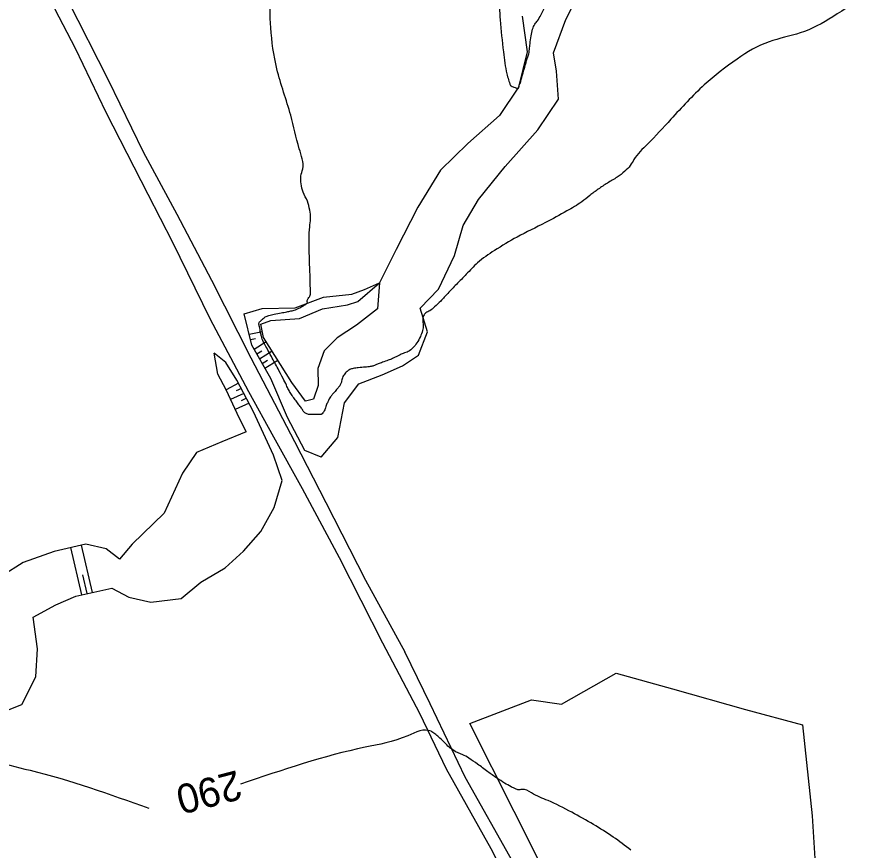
# Model space of a CAD drawing. Extents: x -475575 to -473225, y -1116053 to -1114104.
# Drawn here: x -473778.6 to -473663.7, y -1115005.8 to -1114891.8 of the extents above; entities that cross this region are included whole.
import ezdxf

# ---------------------------------------------------------------- set-up
doc = ezdxf.new("R2010")
doc.units = 0
for name, color, linetype in [('Vrstevnice_hlavni', 7, 'Continuous'), ('Vrstevnice_popis', 7, 'Continuous'), ('Vrstevnice_vedlejsi', 7, 'Continuous'), ('Vrstva_10', 7, 'Continuous')]:
    doc.layers.add(name, color=color, linetype=linetype)

msp = doc.modelspace()

# ---------------------------------------------------------------- linework, layer by layer
at = {"layer": 'Vrstevnice_hlavni'}
for points in [[(-473788.48, -1114990.57), (-473787.7, -1114989.85), (-473787.05, -1114989.73), (-473786.53, -1114990.19), (-473786.14, -1114991.25), (-473785.78, -1114991.95), (-473785.46, -1114992.29), (-473785.18, -1114992.26), (-473782.28, -1114993.11), (-473776.78, -1114994.83), (-473760.55, -1115000.02)], [(-473694.62, -1115005.76), (-473697.04, -1115003.96), (-473699.74, -1115002.24), (-473702.71, -1115000.57), (-473705.95, -1114998.97), (-473708.22, -1114997.93), (-473709.5, -1114997.44), (-473709.81, -1114997.51), (-473710.31, -1114997.39), (-473711.01, -1114997.08), (-473711.89, -1114996.58), (-473712.95, -1114995.9), (-473714.19, -1114995.03), (-473715.6, -1114993.98), (-473716.76, -1114993.19), (-473717.67, -1114992.68), (-473718.33, -1114992.42), (-473718.98, -1114992.04), (-473719.64, -1114991.51), (-473720.29, -1114990.85), (-473720.89, -1114990.29), (-473721.45, -1114989.84), (-473721.95, -1114989.5), (-473725.13, -1114990.11), (-473730.97, -1114991.68), (-473748.01, -1114996.73)], [(-473766.29, -1115102.81), (-473766.71, -1115101.56), (-473767.08, -1115100.43), (-473767.41, -1115099.41), (-473767.7, -1115098.51), (-473768.04, -1115097.46), (-473768.45, -1115096.25), (-473768.91, -1115094.88), (-473769.29, -1115093.72), (-473769.59, -1115092.77), (-473769.8, -1115092.02), (-473770.06, -1115091.24), (-473770.35, -1115090.42), (-473770.68, -1115089.57), (-473771.1, -1115088.3), (-473771.62, -1115086.63), (-473772.24, -1115084.54), (-473772.75, -1115082.84), (-473773.16, -1115081.53), (-473773.46, -1115080.61), (-473773.69, -1115079.78), (-473773.86, -1115079.05), (-473773.96, -1115078.4), (-473774.21, -1115077.4), (-473774.61, -1115076.04), (-473775.15, -1115074.31), (-473775.57, -1115072.9), (-473775.87, -1115071.82), (-473776.05, -1115071.05), (-473776.24, -1115070.27), (-473776.46, -1115069.47), (-473776.7, -1115068.65), (-473777.04, -1115067.5), (-473777.48, -1115066.01), (-473778.01, -1115064.19), (-473778.45, -1115062.69), (-473778.81, -1115061.51), (-473779.09, -1115060.64), (-473779.43, -1115059.49), (-473779.84, -1115058.06), (-473780.31, -1115056.33), (-473780.78, -1115054.75), (-473781.24, -1115053.31), (-473781.69, -1115052.02), (-473782.08, -1115050.93), (-473782.41, -1115050.06), (-473782.67, -1115049.4), (-473782.99, -1115048.4), (-473783.38, -1115047.05), (-473783.84, -1115045.35), (-473784.21, -1115043.9), (-473784.5, -1115042.7), (-473784.7, -1115041.74), (-473784.98, -1115040.58), (-473785.32, -1115039.22), (-473785.72, -1115037.66), (-473786.11, -1115036.27), (-473786.47, -1115035.06), (-473786.82, -1115034.02), (-473787.13, -1115032.91), (-473787.42, -1115031.73), (-473787.68, -1115030.48), (-473787.94, -1115029.23), (-473788.22, -1115027.98), (-473788.51, -1115026.74), (-473788.81, -1115025.47), (-473789.12, -1115024.19), (-473789.45, -1115022.88), (-473789.79, -1115021.56), (-473790.15, -1115020.23), (-473790.52, -1115018.88), (-473790.9, -1115017.5), (-473791.28, -1115016.07), (-473791.67, -1115014.61), (-473792.04, -1115013.08), (-473792.4, -1115011.48), (-473792.74, -1115009.82), (-473793.01, -1115008.27), (-473793.21, -1115006.83), (-473793.33, -1115005.52), (-473793.42, -1115004.39), (-473793.49, -1115003.44), (-473793.52, -1115002.69), (-473793.69, -1115001.84), (-473794, -1115000.92), (-473794.45, -1114999.91), (-473794.77, -1114999.16), (-473794.95, -1114998.68), (-473794.99, -1114998.45), (-473795.09, -1114998.06), (-473795.24, -1114997.52), (-473795.43, -1114996.81), (-473794.85, -1114995.8), (-473793.5, -1114994.49), (-473791.38, -1114992.89), (-473789.71, -1114991.58), (-473788.48, -1114990.57)]]:
    msp.add_spline(points, degree=3, dxfattribs=at)
at = {"layer": 'Vrstevnice_vedlejsi'}
for points in [[(-473806.43, -1114819.38), (-473806.38, -1114819.37), (-473806.1, -1114819.33), (-473805.58, -1114819.26), (-473804.83, -1114819.16), (-473804.26, -1114819.08), (-473803.86, -1114819.01), (-473803.64, -1114818.96), (-473803.42, -1114818.89), (-473803.18, -1114818.82), (-473802.94, -1114818.73), (-473802.51, -1114818.57), (-473801.87, -1114818.32), (-473801.04, -1114817.99), (-473800.27, -1114817.66), (-473799.56, -1114817.32), (-473798.92, -1114816.98), (-473798.15, -1114816.62), (-473797.28, -1114816.25), (-473796.28, -1114815.85), (-473795.35, -1114815.35), (-473794.47, -1114814.75), (-473793.65, -1114814.03), (-473792.88, -1114813.39), (-473792.17, -1114812.84), (-473791.51, -1114812.36), (-473790.85, -1114811.93), (-473790.2, -1114811.53), (-473789.56, -1114811.17), (-473789.11, -1114810.81), (-473788.86, -1114810.45), (-473788.79, -1114810.08), (-473788.78, -1114809.72), (-473788.8, -1114809.36), (-473788.87, -1114809.01), (-473788.92, -1114808.76), (-473788.96, -1114808.61), (-473788.98, -1114808.58), (-473789.06, -1114808.47), (-473789.2, -1114808.3), (-473789.4, -1114808.07), (-473789.38, -1114807.65), (-473789.15, -1114807.05), (-473788.71, -1114806.27), (-473788.35, -1114805.79), (-473788.06, -1114805.62), (-473787.84, -1114805.76), (-473787.63, -1114805.87), (-473787.42, -1114805.95), (-473787.21, -1114805.99), (-473786.5, -1114806.07), (-473785.28, -1114806.2), (-473783.56, -1114806.36), (-473781.6, -1114806.32), (-473779.4, -1114806.07), (-473776.95, -1114805.61), (-473775.18, -1114805.35), (-473774.08, -1114805.27), (-473773.66, -1114805.39), (-473771.91, -1114806.02), (-473768.82, -1114807.16), (-473764.41, -1114808.81), (-473757.99, -1114812.23), (-473749.55, -1114817.42), (-473739.09, -1114824.39), (-473731.16, -1114829.57), (-473725.76, -1114832.96), (-473722.88, -1114834.56), (-473720.56, -1114835.65), (-473718.79, -1114836.23), (-473717.58, -1114836.3), (-473715.64, -1114836.75), (-473712.97, -1114837.58), (-473709.58, -1114838.79), (-473708.57, -1114839.98), (-473709.95, -1114841.15), (-473713.71, -1114842.3), (-473715.46, -1114846.43), (-473715.18, -1114853.56), (-473712.88, -1114863.69), (-473711.43, -1114870.72), (-473710.84, -1114874.67), (-473711.08, -1114875.53), (-473711.23, -1114876.41), (-473711.26, -1114877.31), (-473711.19, -1114878.25), (-473711.12, -1114879.28), (-473711.05, -1114880.42), (-473710.98, -1114881.65), (-473711.16, -1114883.03), (-473711.59, -1114884.54), (-473712.27, -1114886.19), (-473712.58, -1114888.75), (-473712.5, -1114892.22), (-473712.05, -1114896.6), (-473711.58, -1114899.59), (-473711.1, -1114901.19)], [(-473711.1, -1114901.19), (-473710.61, -1114901.41), (-473710.26, -1114901.54), (-473710.06, -1114901.57), (-473710.01, -1114901.53), (-473709.97, -1114901.49), (-473709.95, -1114901.47), (-473709.94, -1114901.46), (-473709.93, -1114901.44), (-473709.93, -1114901.43), (-473709.93, -1114901.42), (-473709.78, -1114900.89), (-473709.47, -1114899.85), (-473709.01, -1114898.29), (-473708.71, -1114897.24), (-473708.55, -1114896.69), (-473708.55, -1114896.64), (-473708.5, -1114896.23), (-473708.41, -1114895.48), (-473708.27, -1114894.37), (-473708.06, -1114893.47), (-473707.77, -1114892.8), (-473707.4, -1114892.33), (-473706.94, -1114891.55), (-473706.39, -1114890.46), (-473705.74, -1114889.05), (-473705.18, -1114887.94), (-473704.69, -1114887.15), (-473704.29, -1114886.65), (-473703.73, -1114886.18), (-473703.01, -1114885.72), (-473702.14, -1114885.28), (-473701.43, -1114884.84), (-473700.89, -1114884.42), (-473700.52, -1114884.01), (-473700.06, -1114883.38), (-473699.49, -1114882.54), (-473698.82, -1114881.48), (-473698.24, -1114880.31), (-473697.76, -1114879.03), (-473697.37, -1114877.62), (-473697.09, -1114876.65), (-473696.93, -1114876.12), (-473696.88, -1114876.01), (-473696.49, -1114875.69), (-473695.76, -1114875.14), (-473694.69, -1114874.37), (-473693.74, -1114873.74), (-473692.92, -1114873.26), (-473692.23, -1114872.91), (-473690.49, -1114869.83), (-473687.7, -1114864.01), (-473683.85, -1114855.45), (-473680.86, -1114849.41), (-473678.72, -1114845.88), (-473677.43, -1114844.86), (-473675.79, -1114843.76), (-473673.8, -1114842.57), (-473671.44, -1114841.28), (-473668.14, -1114838.94), (-473663.87, -1114835.52), (-473658.65, -1114831.05), (-473653.68, -1114827.13), (-473648.95, -1114823.78), (-473644.48, -1114820.98), (-473640.15, -1114820.2), (-473635.99, -1114821.44), (-473631.98, -1114824.7), (-473626.19, -1114826.58), (-473618.64, -1114827.09), (-473609.32, -1114826.22), (-473599.64, -1114826.28), (-473589.6, -1114827.29), (-473579.21, -1114829.24), (-473571.3, -1114830.25), (-473565.87, -1114830.31), (-473562.94, -1114829.43), (-473557.46, -1114829.21), (-473549.43, -1114829.66), (-473548.19, -1114829.78)], [(-473734.16, -1114941.44), (-473734.2, -1114941.76), (-473734.37, -1114942.13), (-473734.66, -1114942.54), (-473735.07, -1114943.01), (-473735.41, -1114943.41), (-473735.68, -1114943.76), (-473735.87, -1114944.05), (-473736.07, -1114944.44), (-473736.28, -1114944.94), (-473736.49, -1114945.55), (-473736.73, -1114945.96), (-473736.97, -1114946.16), (-473737.23, -1114946.17), (-473737.58, -1114946.17), (-473738.03, -1114946.17), (-473738.58, -1114946.18), (-473739.02, -1114946.05), (-473739.36, -1114945.79), (-473739.6, -1114945.41), (-473739.91, -1114944.96), (-473740.29, -1114944.45), (-473740.73, -1114943.88), (-473741.12, -1114943.31), (-473741.44, -1114942.75), (-473741.71, -1114942.18), (-473742.18, -1114941.24), (-473742.87, -1114939.93), (-473743.77, -1114938.26), (-473744.42, -1114937.06), (-473744.81, -1114936.32), (-473744.95, -1114936.06), (-473745.07, -1114935.71), (-473745.19, -1114935.28), (-473745.29, -1114934.77), (-473745.37, -1114934.36), (-473745.44, -1114934.05), (-473745.48, -1114933.84), (-473745.47, -1114933.66), (-473745.41, -1114933.51), (-473745.28, -1114933.4), (-473745.11, -1114933.24), (-473744.89, -1114933.06), (-473744.61, -1114932.84), (-473744.11, -1114932.64), (-473743.39, -1114932.45), (-473742.43, -1114932.28), (-473741.68, -1114932.13), (-473741.13, -1114932.02), (-473740.78, -1114931.93), (-473740.5, -1114931.85), (-473740.28, -1114931.77), (-473740.12, -1114931.7), (-473739.89, -1114931.58), (-473739.58, -1114931.41), (-473739.2, -1114931.18), (-473738.96, -1114930.99), (-473738.86, -1114930.82), (-473738.9, -1114930.68), (-473738.86, -1114930.51), (-473738.76, -1114930.31), (-473738.58, -1114930.08), (-473738.46, -1114929.85), (-473738.41, -1114929.6), (-473738.42, -1114929.35), (-473738.46, -1114928.36), (-473738.51, -1114926.63), (-473738.59, -1114924.15), (-473738.6, -1114922.12), (-473738.54, -1114920.53), (-473738.42, -1114919.38), (-473738.53, -1114918.21), (-473738.86, -1114917.01), (-473739.42, -1114915.78), (-473739.72, -1114914.63), (-473739.74, -1114913.57), (-473739.49, -1114912.59), (-473739.96, -1114909.83), (-473741.14, -1114905.26), (-473743.03, -1114898.91), (-473743.86, -1114893.28), (-473743.63, -1114888.37), (-473742.33, -1114884.19), (-473743.57, -1114878.62), (-473747.35, -1114871.67), (-473753.68, -1114863.33), (-473758.63, -1114857.18), (-473762.22, -1114853.23), (-473764.43, -1114851.47), (-473766.22, -1114850.1), (-473767.58, -1114849.15), (-473768.51, -1114848.59), (-473769.49, -1114848.05), (-473770.53, -1114847.52), (-473771.62, -1114847.01), (-473773.23, -1114846.47), (-473775.36, -1114845.92)], [(-473526.4, -1114874.11), (-473532.36, -1114874.36), (-473544.72, -1114875.73), (-473553.28, -1114876.61), (-473558.05, -1114877), (-473559.03, -1114876.91), (-473560.16, -1114876.71), (-473561.46, -1114876.41), (-473562.92, -1114876.02), (-473567.85, -1114875.52), (-473576.26, -1114874.92), (-473588.13, -1114874.22), (-473599.38, -1114873.36), (-473610, -1114872.35), (-473619.99, -1114871.17), (-473627.77, -1114870.54), (-473633.33, -1114870.45), (-473636.66, -1114870.9), (-473639.51, -1114871.55), (-473641.86, -1114872.37), (-473643.73, -1114873.39), (-473645.76, -1114874.69), (-473647.95, -1114876.27), (-473650.31, -1114878.14), (-473653.5, -1114880.8), (-473657.51, -1114884.27), (-473662.35, -1114888.54), (-473667, -1114891.78), (-473671.46, -1114894), (-473675.73, -1114895.2), (-473680.1, -1114897.56), (-473684.58, -1114901.1), (-473689.15, -1114905.8), (-473692.36, -1114909.21), (-473694.21, -1114911.31), (-473694.7, -1114912.11), (-473695.46, -1114912.92), (-473696.5, -1114913.72), (-473697.83, -1114914.53), (-473699.08, -1114915.36), (-473700.25, -1114916.22), (-473701.34, -1114917.09), (-473703.36, -1114918.34), (-473706.31, -1114919.94), (-473710.18, -1114921.91), (-473713.27, -1114923.75), (-473715.59, -1114925.44), (-473717.13, -1114927), (-473718.48, -1114928.39), (-473719.65, -1114929.61), (-473720.63, -1114930.66), (-473721.46, -1114931.46), (-473722.13, -1114931.99), (-473722.64, -1114932.26), (-473722.96, -1114932.68), (-473723.08, -1114933.24), (-473723.01, -1114933.95), (-473723.11, -1114934.71), (-473723.41, -1114935.52), (-473723.88, -1114936.39), (-473724.43, -1114937.07), (-473725.06, -1114937.55), (-473725.76, -1114937.83), (-473726.28, -1114938.06), (-473726.64, -1114938.24), (-473726.83, -1114938.35), (-473727.21, -1114938.53), (-473727.8, -1114938.76), (-473728.59, -1114939.04), (-473729.18, -1114939.26), (-473729.59, -1114939.43), (-473729.8, -1114939.52), (-473730.25, -1114939.62), (-473730.95, -1114939.7), (-473731.89, -1114939.78), (-473732.59, -1114939.89), (-473733.06, -1114940.02), (-473733.3, -1114940.18), (-473733.53, -1114940.37), (-473733.73, -1114940.6), (-473733.92, -1114940.86), (-473734.06, -1114941.14), (-473734.16, -1114941.44)]]:
    msp.add_spline(points, degree=3, dxfattribs=at)
at = {"layer": 'Vrstva_10'}
for p, q in [((-473746.83, -1114935.18), (-473745, -1114934.82)), ((-473746.65, -1114935.91), (-473745.93, -1114935.77)), ((-473746.14, -1114937.24), (-473744.49, -1114936.2)), ((-473750.02, -1114939.08), (-473751.61, -1114937.8)), ((-473745.77, -1114937.89), (-473745.09, -1114937.47)), ((-473745.39, -1114938.54), (-473743.69, -1114937.48)), ((-473748.49, -1114941.47), (-473750.02, -1114939.08)), ((-473745.02, -1114939.19), (-473744.33, -1114938.76)), ((-473744.65, -1114939.84), (-473742.9, -1114938.75)), ((-473746.22, -1114945.79), (-473748.49, -1114941.47)), ((-473748.28, -1114941.88), (-473749.98, -1114942.78)), ((-473747.53, -1114943.29), (-473749.35, -1114944.14)), ((-473747.88, -1114942.63), (-473748.6, -1114942.96)), ((-473746.83, -1114944.62), (-473748.72, -1114945.5)), ((-473747.18, -1114943.96), (-473747.93, -1114944.3)), ((-473743.48, -1114951.75), (-473746.22, -1114945.79)), ((-473747.22, -1114948.53), (-473750.54, -1114949.93)), ((-473750.54, -1114949.93), (-473754.01, -1114951.39)), ((-473754.01, -1114951.39), (-473755.92, -1114954.22)), ((-473742.31, -1114955.19), (-473743.48, -1114951.75)), ((-473755.92, -1114954.22), (-473758.44, -1114959.67)), ((-473743.39, -1114958.89), (-473742.31, -1114955.19)), ((-473758.44, -1114959.67), (-473762.83, -1114963.92)), ((-473745.23, -1114962.17), (-473743.39, -1114958.89)), ((-473747.57, -1114964.86), (-473745.23, -1114962.17)), ((-473769.16, -1114963.89), (-473773.5, -1114964.9)), ((-473769.71, -1114970.83), (-473771.22, -1114964.37)), ((-473768.25, -1114970.52), (-473769.76, -1114964.03)), ((-473766.35, -1114964.55), (-473769.16, -1114963.89)), ((-473762.83, -1114963.92), (-473764.54, -1114965.97)), ((-473773.5, -1114964.9), (-473777.71, -1114966.4)), ((-473764.54, -1114965.97), (-473766.35, -1114964.55)), ((-473750.1, -1114967.16), (-473747.57, -1114964.86)), ((-473777.71, -1114966.4), (-473780.58, -1114968.26)), ((-473753.44, -1114969.09), (-473750.1, -1114967.16)), ((-473768.98, -1114970.67), (-473769.58, -1114968.08)), ((-473770.5, -1114971), (-473765.6, -1114969.94)), ((-473765.6, -1114969.94), (-473763.25, -1114971.16)), ((-473756.1, -1114971.33), (-473753.44, -1114969.09)), ((-473773.25, -1114972.22), (-473770.5, -1114971)), ((-473763.25, -1114971.16), (-473760.27, -1114971.82)), ((-473760.27, -1114971.82), (-473756.1, -1114971.33)), ((-473776.37, -1114973.9), (-473773.25, -1114972.22)), ((-473775.77, -1114978.21), (-473776.37, -1114973.9)), ((-473775.99, -1114982.03), (-473775.77, -1114978.21)), ((-473777.92, -1114985.82), (-473775.99, -1114982.03)), ((-473782.65, -1114987.71), (-473777.92, -1114985.82))]:
    msp.add_line(p, q, dxfattribs=at)
for points in [[(-473707.84, -1115017.11), (-473713.73, -1115005.55), (-473719.81, -1114994.68), (-473723.46, -1114987.06), (-473728.53, -1114977.44), (-473734.46, -1114965.78), (-473739.51, -1114956.32), (-473743.44, -1114949.29), (-473746.84, -1114943.08), (-473752.17, -1114933.09), (-473757.23, -1114922.66), (-473760.64, -1114916.1), (-473766.39, -1114904.89), (-473770.54, -1114896.1), (-473773.92, -1114889.65), (-473778.38, -1114881.26)], [(-473736.96, -1114952.01), (-473734.67, -1114949.32), (-473733.79, -1114944.6), (-473731.82, -1114941.97), (-473728.64, -1114940.75), (-473725.84, -1114939.5), (-473723.64, -1114938.08), (-473722.44, -1114934.87), (-473723.43, -1114931.63), (-473720.91, -1114929.05), (-473718.73, -1114924.42), (-473717.55, -1114920.32), (-473715.47, -1114916.79), (-473711.8, -1114912.26), (-473707.36, -1114907.23), (-473704.53, -1114903.03), (-473704.81, -1114899.22), (-473705.18, -1114896.7), (-473703.51, -1114892.14), (-473701.43, -1114888.03)], [(-473771.63, -1114889.58), (-473766.11, -1114900.39), (-473761.29, -1114910.27), (-473756.7, -1114918.78), (-473751.98, -1114927.82), (-473746.57, -1114938.43), (-473740.62, -1114949.87), (-473736.35, -1114958.19), (-473730.89, -1114968.85), (-473725.55, -1114978.62)], [(-473709.49, -1114891.69), (-473708.79, -1114896.58), (-473709.98, -1114901.43), (-473712.57, -1114905.28), (-473716.93, -1114909.12), (-473720.66, -1114912.76), (-473723.74, -1114917.81), (-473726.73, -1114923.59), (-473729, -1114928.18), (-473729.28, -1114931.74), (-473732.13, -1114933.98), (-473734.79, -1114935.71), (-473736.58, -1114937.45), (-473737.43, -1114939.9), (-473737.38, -1114942.21), (-473738.04, -1114944.1), (-473739.1, -1114944.36), (-473740.99, -1114941.81), (-473744.84, -1114935.64), (-473745.2, -1114933.83), (-473743.83, -1114933.33), (-473739.94, -1114933.05), (-473736.81, -1114931.73), (-473733.36, -1114931.19), (-473731.94, -1114930.7), (-473729, -1114928.16)], [(-473736.96, -1114952.01), (-473739.19, -1114951.1), (-473741.58, -1114946.58), (-473743.86, -1114941.23), (-473746.46, -1114936.68), (-473747.51, -1114932.43), (-473745.04, -1114931.66), (-473740.53, -1114931.61), (-473736.64, -1114930.12), (-473732.76, -1114929.71), (-473731.04, -1114929.07), (-473729, -1114928.18)], [(-473747.22, -1114948.53), (-473748.47, -1114946.05), (-473749.97, -1114942.8), (-473751.08, -1114940.67), (-473751.61, -1114937.8)], [(-473710.78, -1115007.36), (-473717.26, -1114995.78), (-473722.06, -1114985.73), (-473725.55, -1114978.62)]]:
    msp.add_lwpolyline(points, dxfattribs=at)
msp.add_lwpolyline([(-473666.84, -1115033.79), (-473674.79, -1115038.68), (-473683.53, -1115044.22), (-473687.46, -1115047.24), (-473694.28, -1115033.57), (-473702.5, -1115016.52), (-473710.57, -1115000.48), (-473716.63, -1114988.41), (-473708.21, -1114985.2), (-473704.09, -1114985.78), (-473696.62, -1114981.53), (-473688.93, -1114983.69), (-473678.95, -1114986.51), (-473671.15, -1114988.61), (-473669.82, -1115001.07), (-473669.06, -1115013.47), (-473667.43, -1115027.13)], close=True, dxfattribs=at)

# ---------------------------------------------------------------- texts
at = {"layer": 'Vrstevnice_popis'}
msp.add_text(' 290 ', height=4, rotation=194.701, dxfattribs=at).set_placement((-473747.04, -1114994.41))

doc.saveas('drawing.dxf')
